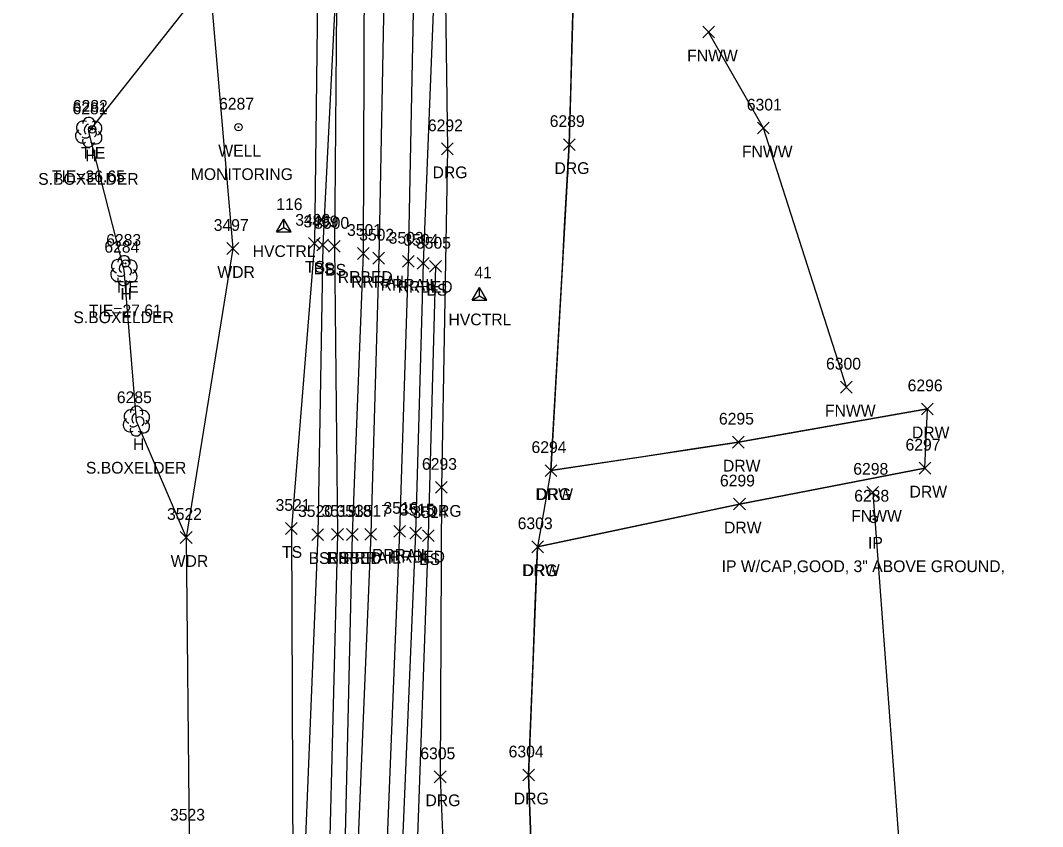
# Model space of a CAD drawing. Extents: x 1462668 to 1465147, y 550359 to 557351.
# Drawn here: x 1464914.5 to 1465088.4, y 551254.6 to 551391.8 of the extents above; entities that cross this region are included whole.
import ezdxf

# ---------------------------------------------------------------- set-up
doc = ezdxf.new("R2010")
doc.units = 0
for name, color, linetype in [('C_A', 7, 'Continuous'), ('C_C', 7, 'Continuous'), ('C_I', 7, 'Continuous'), ('CBP', 7, 'Continuous'), ('CPSM', 7, 'Continuous'), ('L_A', 7, 'Continuous'), ('L_C', 7, 'Continuous'), ('L_I', 7, 'Continuous'), ('L_TIC', 7, 'Continuous'), ('LAWA', 7, 'Continuous'), ('LELB', 7, 'Continuous'), ('Level 6', 7, 'Continuous'), ('LFNC', 7, 'Continuous'), ('LTD', 7, 'Continuous'), ('M_A', 7, 'Continuous'), ('M_C', 7, 'Continuous'), ('M_I', 7, 'Continuous'), ('MPIR', 7, 'Continuous'), ('R_A', 7, 'Continuous'), ('R_I', 7, 'Continuous'), ('R_TIC', 7, 'Continuous'), ('RDG', 7, 'Continuous'), ('RDW', 7, 'Continuous'), ('RR', 7, 'Continuous'), ('RRB', 7, 'Continuous'), ('U_A', 7, 'Continuous'), ('U_C', 7, 'Continuous'), ('U_I', 7, 'Continuous'), ('UWW', 7, 'Continuous')]:
    doc.layers.add(name, color=color, linetype=linetype)

msp = doc.modelspace()

# ---------------------------------------------------------------- linework, layer by layer
at = {"layer": 'CBP'}
for centre, radius in [((1464926.7, 551373.3), 0.625), ((1464926.7, 551373.3), 0.0833), ((1464932.37, 551350.47), 0.625), ((1464932.37, 551350.47), 0.0833)]:
    msp.add_circle(centre, radius, dxfattribs=at)
at = {"layer": 'CPSM'}
for p, q in [((1464958.05, 551355.84), (1464959.3, 551358.01)), ((1464960.55, 551355.84), (1464959.3, 551358.01)), ((1464959.3, 551356.56), (1464959.3, 551358.01)), ((1464958.05, 551355.84), (1464959.3, 551356.56)), ((1464958.05, 551355.84), (1464960.55, 551355.84)), ((1464959.3, 551356.56), (1464959.3, 551356.56)), ((1464959.3, 551356.56), (1464960.55, 551355.84)), ((1464991.37, 551344.21), (1464992.62, 551346.37)), ((1464993.87, 551344.21), (1464992.62, 551346.37)), ((1464992.62, 551344.93), (1464992.62, 551346.37)), ((1464991.37, 551344.21), (1464992.62, 551344.93)), ((1464991.37, 551344.21), (1464993.87, 551344.21)), ((1464992.62, 551344.93), (1464992.62, 551344.93)), ((1464992.62, 551344.93), (1464993.87, 551344.21))]:
    msp.add_line(p, q, dxfattribs=at)
at = {"layer": 'L_TIC'}
for points in [[(1465030.59, 551388.86), (1465032.59, 551390.86)], [(1465032.59, 551388.86), (1465030.59, 551390.86)], [(1465039.91, 551372.51), (1465041.91, 551374.51)], [(1465041.91, 551372.51), (1465039.91, 551374.51)], [(1464949.63, 551352.01), (1464951.63, 551354.01)], [(1464951.63, 551352.01), (1464949.63, 551354.01)], [(1464963.51, 551352.89), (1464965.51, 551354.89)], [(1464965.51, 551352.89), (1464963.51, 551354.89)], [(1464964.92, 551352.61), (1464966.92, 551354.61)], [(1464966.92, 551352.61), (1464964.92, 551354.61)], [(1464966.9, 551352.38), (1464968.9, 551354.38)], [(1464968.9, 551352.38), (1464966.9, 551354.38)], [(1464984.12, 551348.98), (1464986.12, 551350.98)], [(1464986.12, 551348.98), (1464984.12, 551350.98)], [(1465054.04, 551328.4), (1465056.04, 551330.4)], [(1465056.04, 551328.4), (1465054.04, 551330.4)], [(1465058.52, 551310.49), (1465060.52, 551312.49)], [(1465060.52, 551310.49), (1465058.52, 551312.49)], [(1464959.59, 551304.34), (1464961.59, 551306.34)], [(1464961.59, 551304.34), (1464959.59, 551306.34)], [(1464964.07, 551303.3), (1464966.07, 551305.3)], [(1464966.07, 551303.3), (1464964.07, 551305.3)], [(1464967.43, 551303.34), (1464969.43, 551305.34)], [(1464969.43, 551303.34), (1464967.43, 551305.34)], [(1464941.68, 551302.8), (1464943.68, 551304.8)], [(1464943.68, 551302.8), (1464941.68, 551304.8)], [(1464982.89, 551303.12), (1464984.89, 551305.12)], [(1464984.89, 551303.12), (1464982.89, 551305.12)]]:
    msp.add_lwpolyline(points, dxfattribs=at)
at = {"layer": 'LAWA'}
msp.add_lwpolyline([(1464932.61, 551617.11), (1464946.14, 551592.84), (1464950.83, 551545.87), (1464963.4, 551495.44), (1464947.45, 551446.4), (1464946.66, 551398.96), (1464950.63, 551353.01), (1464942.68, 551303.8), (1464943.19, 551252.6), (1464944.1, 551187.61), (1464948.22, 551131.51), (1464943.01, 551091.46), (1464944.29, 551074.84)], dxfattribs=at)
at = {"layer": 'LELB'}
for points in [[(1464914.48, 551872.2), (1464924.48, 551874), (1464927.85, 551872.89), (1464930.43, 551869.97), (1464934.48, 551843.36), (1464939.72, 551807.05), (1464944.24, 551773.43), (1464950.9, 551717.06), (1464955.63, 551678.82), (1464959.4, 551645.2), (1464963.28, 551597.57), (1464964.8, 551546.71), (1464966.53, 551494.93), (1464966.79, 551441.94), (1464968.3, 551401.1), (1464965.92, 551353.61), (1464965.07, 551304.3), (1464962.75, 551247.15), (1464961.36, 551188.58), (1464958.42, 551130.64), (1464955.49, 551094.01), (1464952.56, 551073.69)], [(1464915.57, 551866.45), (1464928, 551869.6), (1464931.76, 551843.59), (1464937.77, 551806.86), (1464942.08, 551772.93), (1464948.71, 551717.27), (1464952.49, 551678.71), (1464957.87, 551644.78), (1464961.45, 551597.92), (1464962.6, 551546.27), (1464963.41, 551495.2), (1464964.92, 551442.3), (1464965.1, 551400.3), (1464964.51, 551353.89), (1464960.59, 551305.34), (1464960.83, 551247.81), (1464957.75, 551187.94), (1464956.49, 551130.72), (1464952.88, 551095.49)], [(1464964.55, 551597.85), (1464966.73, 551546.97), (1464968.88, 551495.34), (1464968.75, 551441.26), (1464968.3, 551401.1), (1464967.9, 551353.38), (1464968.43, 551304.34), (1464966.96, 551246.2), (1464964.89, 551188.84), (1464962.82, 551130.15), (1464958.67, 551094.01), (1464956.17, 551073.95)], [(1464985.12, 551349.98), (1464983.89, 551304.12), (1464981.79, 551244.86), (1464978.93, 551189.13), (1464978.95, 551130.39), (1464978.2, 551081.92), (1464977.52, 551073.9), (1464977.74, 551071.27)]]:
    msp.add_lwpolyline(points, dxfattribs=at)
at = {"layer": 'Level 6'}
for points in [[(1464946.66, 551398.96), (1464926.08, 551372.86), (1464932.07, 551349.3), (1464934.19, 551323.68), (1464942.68, 551303.8), (1464943.19, 551252.6)], [(1465001.51, 551247.89), (1465001.23, 551255.62), (1465000.95, 551263.36), (1465001.33, 551273.07), (1465001.72, 551282.79), (1465002.1, 551292.5), (1465002.49, 551302.22), (1465011.07, 551304.04), (1465019.66, 551305.86), (1465028.25, 551307.68), (1465036.84, 551309.5), (1465044.73, 551311.03), (1465052.62, 551312.56), (1465060.51, 551314.09), (1465068.41, 551315.61), (1465068.82, 551325.7), (1465060.78, 551324.28), (1465052.74, 551322.87), (1465044.7, 551321.45), (1465036.66, 551320.03), (1465028.68, 551318.82), (1465020.71, 551317.61), (1465012.73, 551316.4), (1465004.76, 551315.19), (1465005.15, 551322.13), (1465005.54, 551329.07), (1465005.93, 551336), (1465006.31, 551342.94), (1465006.7, 551349.88), (1465007.09, 551356.82), (1465007.48, 551363.76), (1465007.87, 551370.7), (1465008.12, 551379.91), (1465008.37, 551389.12), (1465008.63, 551398.33)]]:
    msp.add_lwpolyline(points, dxfattribs=at)
at = {"layer": 'LFNC'}
for points in [[(1465055.04, 551329.4), (1465040.91, 551373.51), (1465031.59, 551389.86)], [(1465059.52, 551311.49), (1465065.12, 551236.79), (1465069.86, 551178.31)]]:
    msp.add_lwpolyline(points, dxfattribs=at)
at = {"layer": 'LTD'}
for p, q in [((1464926.08, 551372.86), (1464926.08, 551372.86)), ((1464926.08, 551372.86), (1464926.08, 551372.86)), ((1464932.07, 551349.3), (1464932.07, 551349.3)), ((1464932.07, 551349.3), (1464932.07, 551349.3)), ((1464934.19, 551323.68), (1464934.19, 551323.68)), ((1464934.19, 551323.68), (1464934.19, 551323.68))]:
    msp.add_line(p, q, dxfattribs=at)
for centre in [(1464926.12, 551374.3), (1464932.12, 551350.73), (1464934.24, 551325.11)]:
    msp.add_arc(centre, 1.05, 335.5272, 180.9563, dxfattribs=at)
for centre, major_axis, ratio, start_param, end_param in [((1464925.29, 551373.53), (1.21, -0.51), 0.895232, 1.570796, 4.712389), ((1464924.99, 551372.15), (0.58, -1.04), 0.959034, 3.141593, 6.283185), ((1464925.87, 551373.32), (-0.208, -0.792), 0.645439, 3.141593, 6.283185), ((1464926.58, 551372.7), (-0.5, 0.667), 0.989748, 3.141593, 6.283185), ((1464927.12, 551373.45), (-1.14, -0.48), 0.949671, 1.570796, 4.712389), ((1464926.08, 551371.36), (0.26, 1.06), 0.942809, 1.570796, 4.712389), ((1464925.62, 551372.11), (-0.625, -0.083), 0.423636, 0, 3.141593), ((1464927.08, 551372.03), (-1.09, 0.79), 0.841452, 1.570796, 4.712389), ((1464931.28, 551349.96), (1.21, -0.51), 0.895232, 1.570796, 4.712389), ((1464931.86, 551349.75), (-0.208, -0.792), 0.645439, 3.141593, 6.283185), ((1464933.11, 551349.88), (-1.14, -0.48), 0.949671, 1.570796, 4.712389), ((1464930.99, 551348.59), (0.58, -1.04), 0.959034, 3.141593, 6.283185), ((1464932.57, 551349.13), (-0.5, 0.667), 0.989748, 3.141593, 6.283185), ((1464933.07, 551348.46), (-1.09, 0.79), 0.841452, 1.570796, 4.712389), ((1464932.07, 551347.8), (0.26, 1.06), 0.942809, 1.570796, 4.712389), ((1464931.61, 551348.55), (-0.625, -0.083), 0.423636, 0, 3.141593), ((1464933.4, 551324.34), (1.21, -0.51), 0.895232, 1.570796, 4.712389), ((1464933.99, 551324.13), (-0.208, -0.792), 0.645439, 3.141593, 6.283185), ((1464934.69, 551323.51), (-0.5, 0.667), 0.989748, 3.141593, 6.283185), ((1464935.24, 551324.26), (-1.14, -0.48), 0.949671, 1.570796, 4.712389), ((1464933.11, 551322.97), (0.58, -1.04), 0.959034, 3.141593, 6.283185), ((1464933.74, 551322.93), (-0.625, -0.083), 0.423636, 0, 3.141593), ((1464935.19, 551322.84), (-1.09, 0.79), 0.841452, 1.570796, 4.712389), ((1464934.19, 551322.18), (0.26, 1.06), 0.942809, 1.570796, 4.712389)]:
    msp.add_ellipse(centre, major_axis=major_axis, ratio=ratio, start_param=start_param, end_param=end_param, dxfattribs=at)
at = {"layer": 'MPIR'}
for radius in [0.625, 0.0833]:
    msp.add_circle((1465059.67, 551306.91), radius, dxfattribs=at)
at = {"layer": 'R_TIC'}
for points in [[(1465006.87, 551369.7), (1465008.87, 551371.7)], [(1465008.87, 551369.7), (1465006.87, 551371.7)], [(1465006.87, 551369.7), (1465008.87, 551371.7)], [(1465008.87, 551369.7), (1465006.87, 551371.7)], [(1464986.13, 551368.98), (1464988.13, 551370.98)], [(1464988.13, 551368.98), (1464986.13, 551370.98)], [(1464971.83, 551351.16), (1464973.83, 551353.16)], [(1464973.83, 551351.16), (1464971.83, 551353.16)], [(1464974.46, 551350.36), (1464976.46, 551352.36)], [(1464976.46, 551350.36), (1464974.46, 551352.36)], [(1464979.47, 551349.83), (1464981.47, 551351.83)], [(1464981.47, 551349.83), (1464979.47, 551351.83)], [(1464982.01, 551349.49), (1464984.01, 551351.49)], [(1464984.01, 551349.49), (1464982.01, 551351.49)], [(1465067.82, 551324.7), (1465069.82, 551326.7)], [(1465069.82, 551324.7), (1465067.82, 551326.7)], [(1465035.66, 551319.03), (1465037.66, 551321.03)], [(1465037.66, 551319.03), (1465035.66, 551321.03)], [(1465003.76, 551314.19), (1465005.76, 551316.19)], [(1465005.76, 551314.19), (1465003.76, 551316.19)], [(1465003.76, 551314.19), (1465005.76, 551316.19)], [(1465005.76, 551314.19), (1465003.76, 551316.19)], [(1465067.41, 551314.61), (1465069.41, 551316.61)], [(1465069.41, 551314.61), (1465067.41, 551316.61)], [(1464985.12, 551311.33), (1464987.12, 551313.33)], [(1464987.12, 551311.33), (1464985.12, 551313.33)], [(1465035.84, 551308.5), (1465037.84, 551310.5)], [(1465037.84, 551308.5), (1465035.84, 551310.5)], [(1464969.96, 551303.31), (1464971.96, 551305.31)], [(1464971.96, 551303.31), (1464969.96, 551305.31)], [(1464973.1, 551303.36), (1464975.1, 551305.36)], [(1464975.1, 551303.36), (1464973.1, 551305.36)], [(1464978, 551303.85), (1464980, 551305.85)], [(1464980, 551303.85), (1464978, 551305.85)], [(1464980.72, 551303.54), (1464982.72, 551305.54)], [(1464982.72, 551303.54), (1464980.72, 551305.54)], [(1465001.49, 551301.22), (1465003.49, 551303.22)], [(1465003.49, 551301.22), (1465001.49, 551303.22)], [(1465001.49, 551301.22), (1465003.49, 551303.22)], [(1465003.49, 551301.22), (1465001.49, 551303.22)], [(1464984.91, 551262.05), (1464986.91, 551264.05)], [(1464986.91, 551262.05), (1464984.91, 551264.05)], [(1464999.95, 551262.36), (1465001.95, 551264.36)], [(1465001.95, 551262.36), (1464999.95, 551264.36)]]:
    msp.add_lwpolyline(points, dxfattribs=at)
at = {"layer": 'RDG'}
for points in [[(1465003.62, 551555.57), (1465011.85, 551491.27), (1465009.89, 551444.37), (1465007.87, 551370.7)], [(1464982.38, 551474.17), (1464986.33, 551432.77), (1464987.13, 551369.98), (1464986.12, 551312.33), (1464985.91, 551263.05), (1464987.34, 551228.97), (1464997.78, 551186.27), (1465019.82, 551147.97), (1465035.78, 551121.29), (1465053.95, 551092.09), (1465070.14, 551076.15), (1465084.43, 551065.43)], [(1465007.87, 551370.7), (1465004.76, 551315.19), (1465002.49, 551302.22), (1465000.95, 551263.36), (1465002.06, 551232.41), (1465010.64, 551198.4), (1465033.54, 551158.05), (1465048.9, 551128.97), (1465069.93, 551101), (1465088.42, 551086.34)]]:
    msp.add_lwpolyline(points, dxfattribs=at)
at = {"layer": 'RDW'}
for points in [[(1465004.76, 551315.19), (1465036.66, 551320.03), (1465068.82, 551325.7)], [(1465068.41, 551315.61), (1465036.84, 551309.5), (1465002.49, 551302.22)]]:
    msp.add_lwpolyline(points, dxfattribs=at)
at = {"layer": 'RR'}
for points in [[(1464971.72, 551598.58), (1464974.51, 551547.48), (1464976.08, 551495.67), (1464976.8, 551440.55), (1464976.41, 551401.37), (1464975.46, 551351.36), (1464974.1, 551304.36), (1464971.67, 551245.75), (1464969.32, 551189.1), (1464966.9, 551130.31), (1464964.48, 551072.93)], [(1464976.54, 551599.09), (1464979.47, 551547.89), (1464981.13, 551495.92), (1464981.74, 551440.28), (1464981.51, 551401.87), (1464980.47, 551350.83), (1464979, 551304.85), (1464976.58, 551245.53), (1464974.21, 551189.24), (1464971.81, 551130.66), (1464969.44, 551072.82)]]:
    msp.add_lwpolyline(points, dxfattribs=at)
at = {"layer": 'RRB'}
for points in [[(1464968.39, 551597.95), (1464970.75, 551547.2), (1464973.34, 551495.18), (1464973.65, 551440.8), (1464972.99, 551400.96), (1464972.83, 551352.16), (1464970.96, 551304.31), (1464969.58, 551245.88), (1464967.01, 551188.88), (1464964.91, 551130.44), (1464963.05, 551073.4)], [(1464984.91, 551440.2), (1464985.08, 551401.95), (1464983.01, 551350.49), (1464981.72, 551304.54), (1464979.2, 551245.34), (1464976.51, 551189.35), (1464973.78, 551130.78), (1464971.94, 551073.48)]]:
    msp.add_lwpolyline(points, dxfattribs=at)
at = {"layer": 'UWW'}
for radius in [0.625, 0.0833]:
    msp.add_circle((1464951.58, 551373.67), radius, dxfattribs=at)

# ---------------------------------------------------------------- texts
at = {"layer": 'C_A'}
for s, p in [('TIE', (1464924.77, 551368.3)), ('HVCTRL', (1464954, 551351.56)), ('TIE', (1464930.45, 551345.47)), ('HVCTRL', (1464987.32, 551339.93))]:
    msp.add_text(s, height=2, dxfattribs=at).set_placement(p)
at = {"layer": 'C_C'}
for s, p in [('TIE=36.65', (1464919.83, 551364.3)), ('TIE=27.61', (1464926.12, 551341.47))]:
    msp.add_text(s, height=2, dxfattribs=at).set_placement(p)
at = {"layer": 'C_I'}
for s, p in [('6282', (1464923.39, 551376.3)), ('116', (1464958.02, 551359.56)), ('6283', (1464929.07, 551353.47)), ('41', (1464991.73, 551347.93))]:
    msp.add_text(s, height=2, dxfattribs=at).set_placement(p)
at = {"layer": 'L_A'}
for s, p in [('FNWW', (1465027.94, 551384.86)), ('H', (1464925.51, 551367.86)), ('FNWW', (1465037.26, 551368.51)), ('TS', (1464962.91, 551348.89)), ('BS', (1464964.36, 551348.61)), ('WDR', (1464947.99, 551348.01)), ('BS', (1464966.34, 551348.38)), ('BS', (1464983.57, 551344.98)), ('H', (1464931.5, 551344.3)), ('FNWW', (1465051.39, 551324.4)), ('H', (1464933.63, 551318.68)), ('FNWW', (1465055.86, 551306.49)), ('TS', (1464959, 551300.34)), ('WDR', (1464940.05, 551298.8)), ('BS', (1464963.51, 551299.3)), ('BS', (1464966.88, 551299.34)), ('BS', (1464982.34, 551299.12))]:
    msp.add_text(s, height=2, dxfattribs=at).set_placement(p)
at = {"layer": 'L_C'}
for p in [(1464917.5, 551363.86), (1464923.49, 551340.3), (1464925.62, 551314.68)]:
    msp.add_text('S.BOXELDER', height=2, dxfattribs=at).set_placement(p)
at = {"layer": 'L_I'}
for s, p in [('6301', (1465038.09, 551376.51)), ('6281', (1464923.34, 551375.86)), ('3497', (1464947.37, 551356.01)), ('3498', (1464961.25, 551356.89)), ('3499', (1464962.65, 551356.61)), ('3500', (1464964.47, 551356.38)), ('6284', (1464928.76, 551352.3)), ('3505', (1464981.79, 551352.98)), ('6300', (1465051.57, 551332.4)), ('6285', (1464930.89, 551326.68)), ('6298', (1465056.21, 551314.49)), ('3522', (1464939.42, 551306.8)), ('3521', (1464957.9, 551308.34)), ('3520', (1464961.72, 551307.3)), ('3519', (1464965.73, 551307.34)), ('3514', (1464981.2, 551307.12)), ('3523', (1464939.93, 551255.6))]:
    msp.add_text(s, height=2, dxfattribs=at).set_placement(p)
at = {"layer": 'M_A'}
msp.add_text('IP', height=2, dxfattribs=at).set_placement((1465058.72, 551301.91))
at = {"layer": 'M_C'}
msp.add_text('IP W/CAP,GOOD, 3" ABOVE GROUND,', height=2, dxfattribs=at).set_placement((1465033.81, 551297.91))
at = {"layer": 'M_I'}
msp.add_text('6288', height=2, dxfattribs=at).set_placement((1465056.37, 551309.91))
at = {"layer": 'R_A'}
for s, p in [('DRG', (1464984.61, 551364.98)), ('DRG', (1465005.36, 551365.7)), ('DRG', (1465005.36, 551365.7)), ('RRBED', (1464968.48, 551347.16)), ('RRRAIL', (1464970.75, 551346.36)), ('RRRAIL', (1464975.77, 551345.83)), ('RRBED', (1464978.66, 551345.49)), ('DRW', (1465066.19, 551320.7)), ('DRW', (1465034.03, 551315.03)), ('DRG', (1465002.25, 551310.19)), ('DRW', (1465065.78, 551310.61)), ('DRW', (1465002.13, 551310.19)), ('DRG', (1464983.61, 551307.33)), ('DRW', (1465034.21, 551304.5)), ('RRRAIL', (1464974.3, 551299.85)), ('RRBED', (1464966.61, 551299.31)), ('RRRAIL', (1464969.39, 551299.36)), ('RRBED', (1464977.36, 551299.54)), ('DRW', (1464999.86, 551297.22)), ('DRG', (1464999.97, 551297.22)), ('DRG', (1464983.4, 551258.05)), ('DRG', (1464998.44, 551258.36))]:
    msp.add_text(s, height=2, dxfattribs=at).set_placement(p)
at = {"layer": 'R_I'}
for s, p in [('6292', (1464983.82, 551372.98)), ('6289', (1465004.55, 551373.7)), ('6289', (1465004.55, 551373.7)), ('3501', (1464970.06, 551355.16)), ('3502', (1464972.12, 551354.36)), ('3503', (1464977.14, 551353.83)), ('3504', (1464979.67, 551353.49)), ('6296', (1465065.46, 551328.7)), ('6295', (1465033.35, 551323.03)), ('6294', (1465001.45, 551318.19)), ('6294', (1465001.45, 551318.19)), ('6297', (1465065.1, 551318.61)), ('6293', (1464982.81, 551315.33)), ('6299', (1465033.52, 551312.5)), ('3518', (1464968.27, 551307.31)), ('3517', (1464971.41, 551307.36)), ('3516', (1464976.26, 551307.85)), ('3515', (1464979.02, 551307.54)), ('6303', (1464999.1, 551305.22)), ('6303', (1464999.1, 551305.22)), ('6305', (1464982.53, 551266.05)), ('6304', (1464997.56, 551266.36))]:
    msp.add_text(s, height=2, dxfattribs=at).set_placement(p)
at = {"layer": 'U_A'}
msp.add_text('WELL', height=2, dxfattribs=at).set_placement((1464948.15, 551368.67))
at = {"layer": 'U_C'}
msp.add_text('MONITORING', height=2, dxfattribs=at).set_placement((1464943.47, 551364.67))
at = {"layer": 'U_I'}
msp.add_text('6287', height=2, dxfattribs=at).set_placement((1464948.28, 551376.67))

doc.saveas('drawing.dxf')
